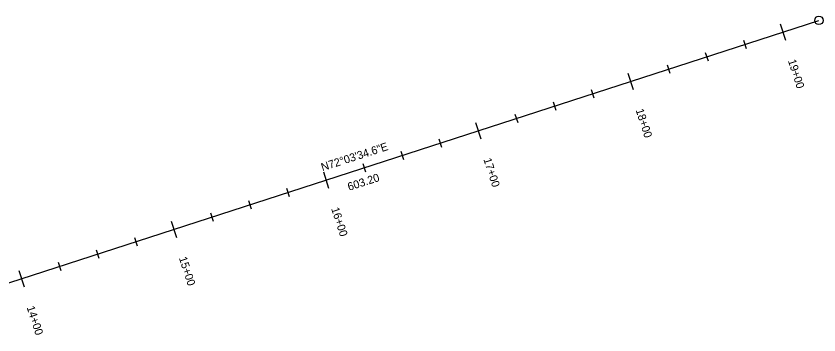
# Model space of a CAD drawing. Extents: x 2300830 to 2307917, y 756066 to 766359.
# Drawn here: x 2303744 to 2304246, y 760435 to 760634 of the extents above; entities that cross this region are included whole.
import ezdxf

# ---------------------------------------------------------------- set-up
doc = ezdxf.new("R2010")
doc.units = 0
for name, color, linetype in [('Default', 7, 'Continuous'), ('Draft_Bearing Label', 7, 'Continuous'), ('Draft_Station Cardinal Points', 7, 'Continuous'), ('Draft_Station Labels Major', 7, 'Continuous'), ('Draft_Station Ticks Major', 7, 'Continuous'), ('Draft_Station Ticks Minor', 7, 'Continuous'), ('Geom_Baseline', 7, 'Continuous')]:
    doc.layers.add(name, color=color, linetype=linetype)

msp = doc.modelspace()

# ---------------------------------------------------------------- linework, layer by layer
at = {"layer": 'Default'}
msp.add_line((2303672.28, 760445.62), (2304246.15, 760631.42), dxfattribs=at)
at = {"layer": 'Draft_Station Cardinal Points'}
msp.add_circle((2304246.15, 760631.42), 2.67, dxfattribs=at)
at = {"layer": 'Draft_Station Ticks Major'}
for p, q in [((2304221.91, 760629.19), (2304225.18, 760619.09)), ((2304126.77, 760598.39), (2304130.04, 760588.28)), ((2304031.63, 760567.58), (2304034.9, 760557.48)), ((2303936.5, 760536.78), (2303939.77, 760526.68)), ((2303841.36, 760505.98), (2303844.63, 760495.87)), ((2303746.22, 760475.18), (2303749.49, 760465.07))]:
    msp.add_line(p, q, dxfattribs=at)
at = {"layer": 'Draft_Station Ticks Minor'}
for p, q in [((2304198.92, 760619.03), (2304200.62, 760613.78)), ((2304175.13, 760611.33), (2304176.83, 760606.08)), ((2304151.35, 760603.63), (2304153.05, 760598.38)), ((2304103.78, 760588.23), (2304105.48, 760582.98)), ((2304080, 760580.53), (2304081.7, 760575.28)), ((2304056.21, 760572.83), (2304057.91, 760567.58)), ((2304008.64, 760557.43), (2304010.34, 760552.18)), ((2303984.86, 760549.73), (2303986.56, 760544.48)), ((2303961.07, 760542.03), (2303962.77, 760536.78)), ((2303913.51, 760526.63), (2303915.21, 760521.37)), ((2303889.72, 760518.93), (2303891.42, 760513.67)), ((2303865.94, 760511.22), (2303867.64, 760505.97)), ((2303818.37, 760495.82), (2303820.07, 760490.57)), ((2303794.58, 760488.12), (2303796.28, 760482.87)), ((2303770.8, 760480.42), (2303772.5, 760475.17))]:
    msp.add_line(p, q, dxfattribs=at)
at = {"layer": 'Geom_Baseline'}
msp.add_line((2303672.28, 760445.62), (2304246.15, 760631.42), dxfattribs=at)

# ---------------------------------------------------------------- texts
at = {"layer": 'Draft_Bearing Label'}
for s, p in [('N72°03\'34.6"E', (2303935.96, 760537.18)), ('603.20', (2303952.56, 760524.93))]:
    msp.add_text(s, height=5, rotation=17.9404, dxfattribs=at).set_placement(p)
at = {"layer": 'Draft_Station Labels Major'}
for s, p in [('19+00', (2304226.72, 760606.21)), ('18+00', (2304131.58, 760575.41)), ('17+00', (2304036.44, 760544.61)), ('16+00', (2303941.31, 760513.81)), ('15+00', (2303846.17, 760483)), ('14+00', (2303751.03, 760452.2))]:
    msp.add_text(s, height=5, rotation=287.9404, dxfattribs=at).set_placement(p)

doc.saveas('drawing.dxf')
